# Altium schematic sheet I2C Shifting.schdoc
size 136 x 58 mm
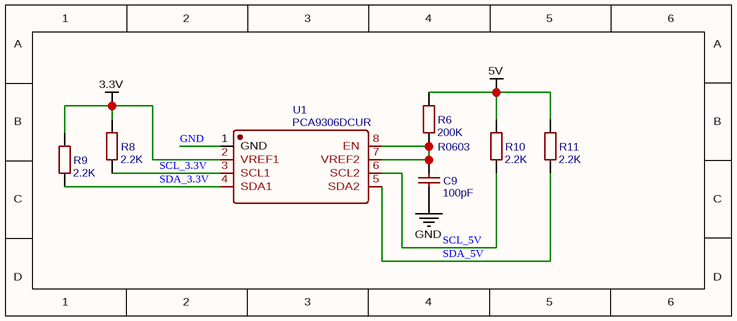
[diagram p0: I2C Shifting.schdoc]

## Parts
C9  100pF  [C0402]
R6  200K  [R0603]
R8  2.2K  [R0402]
R9  2.2K  [R0402]
R10  2.2K  [R0402]
R11  2.2K  [R0402]
U1  PCA9306DCUR  [VSSOP-8_L2.4-W2.1-P0.50-LS3.2-BL]

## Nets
3.3V: R8.2 R9.2 U1.2(VREF1)
5V: R6.2 R10.2 R11.2
GND: C9.1 U1.1(GND)
SCL_3.3V: R8.1 U1.3(SCL1)
SCL_5V: R10.1 U1.6(SCL2)
SDA_3.3V: R9.1 U1.4(SDA1)
SDA_5V: R11.1 U1.5(SDA2)
NetC9_2: C9.2 R6.1 U1.7(VREF2) U1.8(EN)

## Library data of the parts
C9 = 100pF: BOM_Manufacturer: FH; BOM_Manufacturer Part: 0402CG101J500NT; nameAlias: Capacitance; SMT Type: Basic
R6 = 200K: BOM_Manufacturer: UniOhm; BOM_Manufacturer Part: 0603WAF2003T5E; nameAlias: Resistance (Ohms); SMT Type: Basic; Package Display: Yes
R8-R11 = 2.2K: BOM_Manufacturer: UniOhm; BOM_Manufacturer Part: 0402WGF2201TCE; nameAlias: Resistance (Ohms); SMT Type: Basic
U1 = PCA9306DCUR: BOM_Manufacturer: TI; SMT Type: Extend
